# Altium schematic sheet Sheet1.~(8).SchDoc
size A4
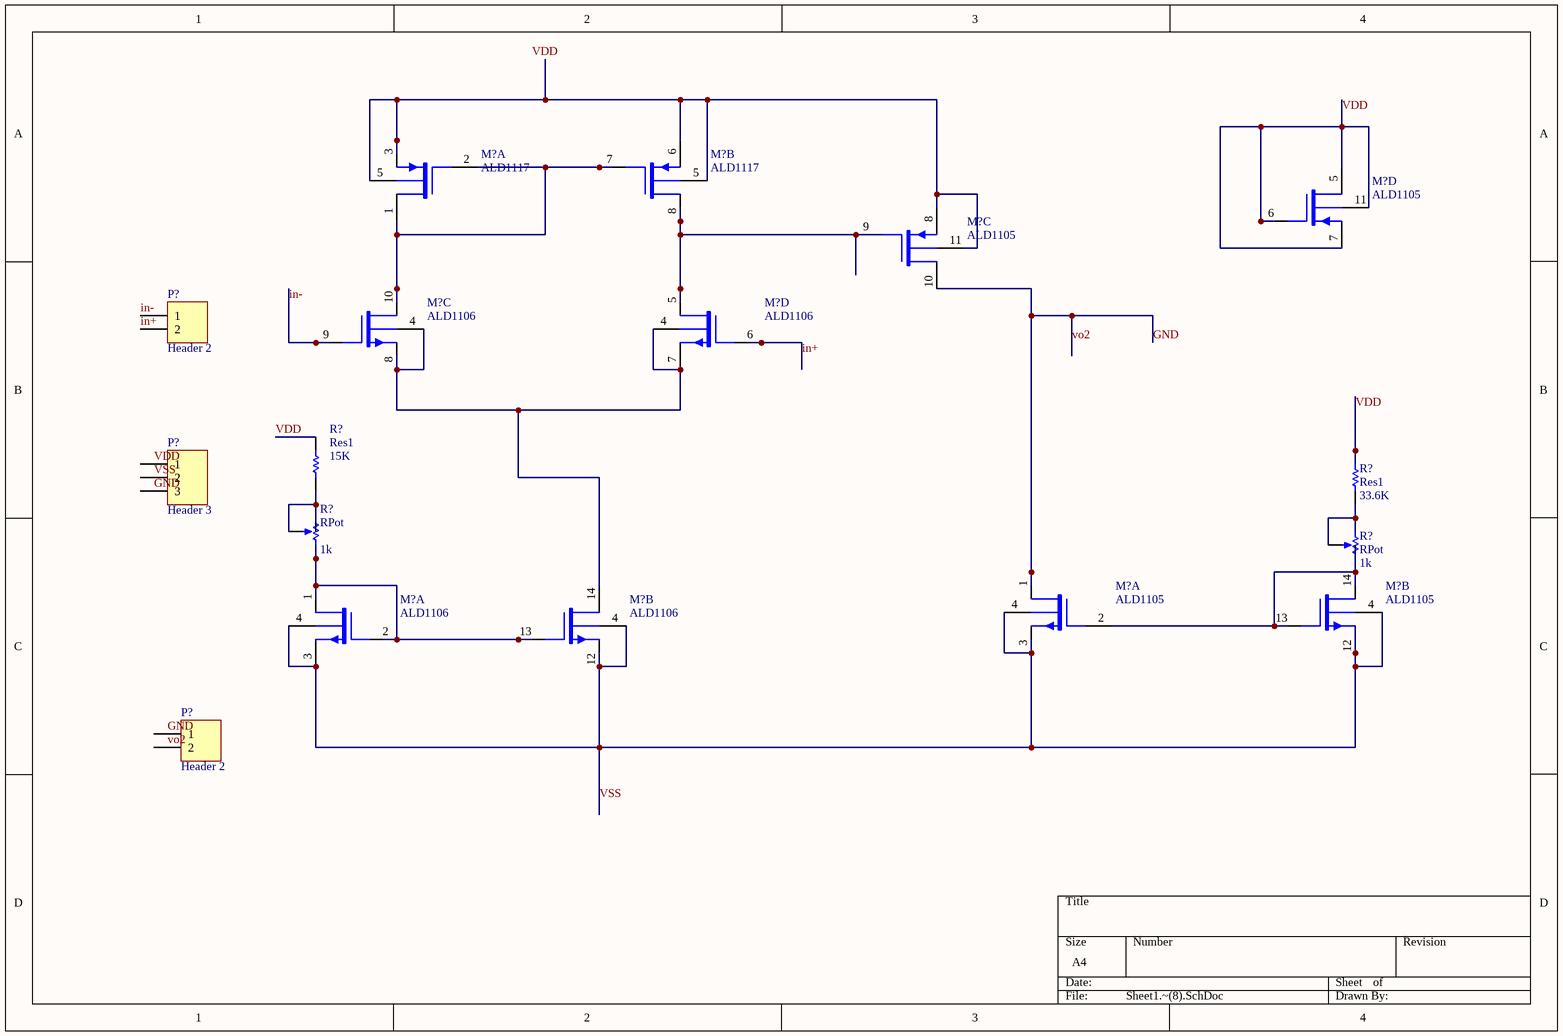
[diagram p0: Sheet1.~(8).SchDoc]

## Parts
(Parts that share a designator on the sheet are numbered #1, #2 ... from top to bottom, then left to right.)
M?#1  ALD1117  [DIP-8]  (part A of 2)
M?#2  ALD1117  [DIP-8]  (part B of 2)
M?#3  ALD1105  [DIP-14]  (part D of 4)
M?#4  ALD1105  [DIP-14]  (part C of 4)
M?#5  ALD1106  [DIP-14]  (part C of 4)
M?#6  ALD1106  [DIP-14]  (part D of 4)
M?#7  ALD1105  [DIP-14]  (part A of 4)
M?#8  ALD1105  [DIP-14]  (part B of 4)
M?#9  ALD1106  [DIP-14]  (part A of 4)
M?#10  ALD1106  [DIP-14]  (part B of 4)
P?#1  Header 2  [HDR1X2]
P?#2  Header 3  [HDR1X3]
P?#3  Header 2  [HDR1X2]
R?#1  Res1  value 15K  [AXIAL-0.3]
R?#2  Res1  value 33.6K  [AXIAL-0.3]
R?#3  RPot  value 1k  [VR5]
R?#4  RPot  value 1k  [VR5]

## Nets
GND: M?#4.10(DP2) M?#7.1(DN1)  [also labelled vo2]
in+: M?#6.6(GN4) P?#1.2
in-: M?#5.9(GN3) P?#1.1
VDD: M?#3.5(DP1) M?#3.6(GP1) M?#3.7(SP1) M?#3.11(V+) R?#1.2 R?#2.2
VSS: M?#7.3(SN1) M?#7.4(V-) M?#8.4(V-) M?#8.12(SN2) M?#9.3(SN1) M?#9.4(V-) M?#10.4(V-) M?#10.12(SN2)
NetM?#1_1: M?#1.1(DP1) M?#1.2(GP1) M?#2.7(GP2) M?#5.10(DN3)
NetM?#1_3: M?#1.3(SP1) M?#1.5(V+) M?#2.5(V+) M?#2.6(SP2) M?#4.8(SP2) M?#4.11(V+)
NetM?#2_8: M?#2.8(DP2) M?#4.9(GP2) M?#6.5(DN4)
NetM?#5_4: M?#5.4(V-) M?#5.8(SN3) M?#6.4(V-) M?#6.7(SN4) M?#10.14(DN2)
NetM?#7_2: M?#7.2(GN1) M?#8.13(GN2) M?#8.14(DN2) R?#4.3(BOT)
NetM?#9_1: M?#9.1(DN1) M?#9.2(GN1) M?#10.13(GN2) R?#3.3(BOT)
NetR?#1_1: R?#1.1 R?#3.1(TOP) R?#3.2(TAP)
NetR?#2_1: R?#2.1 R?#4.1(TOP) R?#4.2(TAP)

Not connected (* = marked no-connect by the designer): P?#2 1 2 3; P?#3 1 2

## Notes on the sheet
- Labels drawn without touching a wire or pin: GND, VDD, vo2, VSS

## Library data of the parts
M?#1 M?#2 = ALD1117: Dual P-channel matched MOSFET array
M?#3 M?#4 M?#7 M?#8 = ALD1105: Dual P-channel and dual N-channel matched MOSFET array
M?#5 M?#6 M?#9 M?#10 = ALD1106: Quad N-channel matched MOSFET array
P?#1 P?#3 = Header 2: Header, 2-Pin
P?#2 = Header 3: Header, 3-Pin
R?#1 R?#2 = Res1: Resistor
R?#3 R?#4 = RPot: Potentiometer; Sim Note: Enter the Resistance value and the set point into parameter fields.; Set Position: 0.5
